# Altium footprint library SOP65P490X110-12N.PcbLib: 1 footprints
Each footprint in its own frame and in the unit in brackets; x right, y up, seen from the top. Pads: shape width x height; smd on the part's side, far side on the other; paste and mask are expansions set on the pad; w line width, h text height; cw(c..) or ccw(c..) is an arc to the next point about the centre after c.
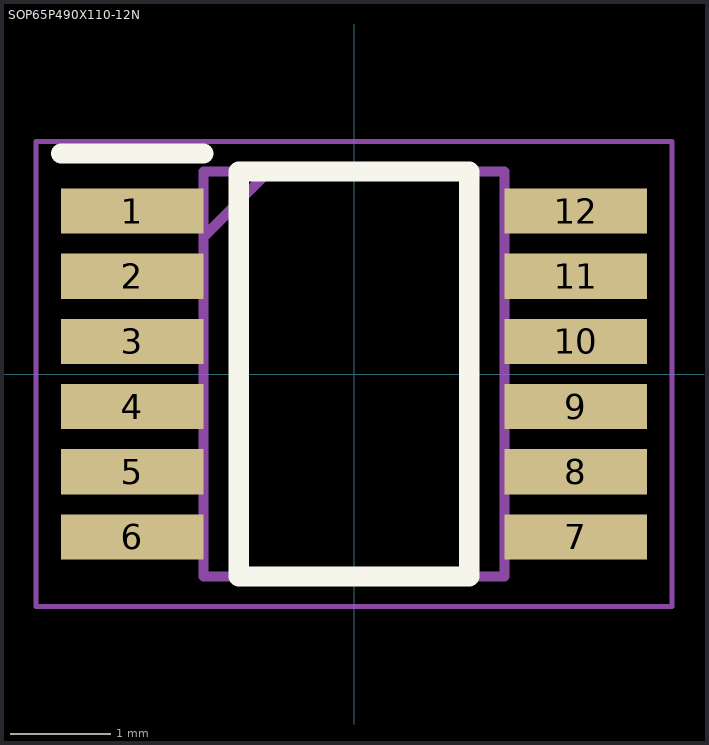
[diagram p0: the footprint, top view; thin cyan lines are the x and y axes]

## SOP65P490X110-12N [mm]
pads (12):
  rect 1.425x0.45 smd: 1(-2.212,1.625) 2(-2.212,0.975) 3(-2.212,0.325) 4(-2.212,-0.325) 5(-2.212,-0.975) 6(-2.212,-1.625) 7(2.212,-1.625) 8(2.212,-0.975) 9(2.212,-0.325) 10(2.212,0.325) 11(2.212,0.975) 12(2.212,1.625)
Top Overlay:
  lines w0.2: -2.925,2.2 -1.5,2.2 ; -1.15,-2.02 1.15,-2.02 1.15,2.02 -1.15,2.02 -1.15,-2.02
Mechanical 15:
  lines w0.1: -1.5,1.37 -0.85,2.02 ; -1.5,-2.02 1.5,-2.02 1.5,2.02 -1.5,2.02 -1.5,-2.02
Mechanical 20:
  lines w0.05: -3.175,-2.32 3.175,-2.32 3.175,2.32 -3.175,2.32 -3.175,-2.32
